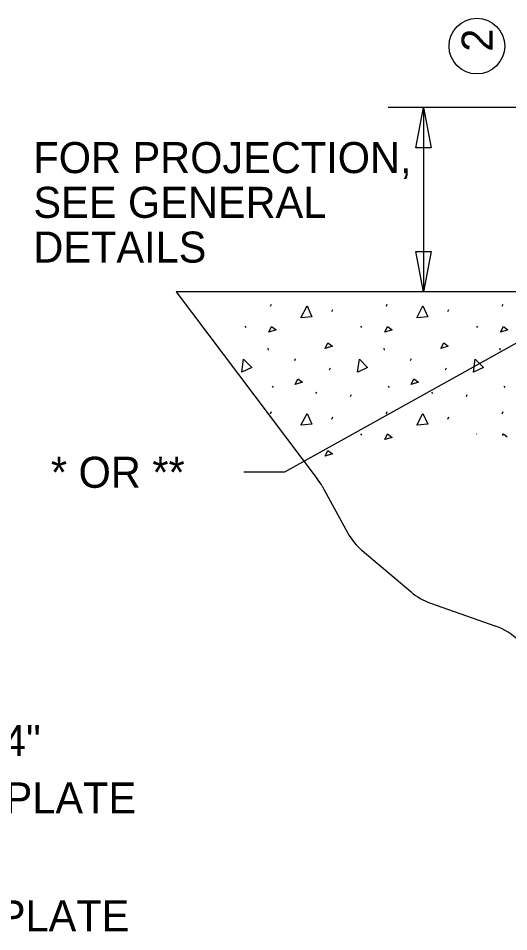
# Model space of a CAD drawing. Extents: x -125.5 to -89.4, y -5.1 to 16.9.
# Drawn here: x -120.383 to -118.408, y 10.396 to 14.074 of the extents above; entities that cross this region are included whole.
import ezdxf

# ---------------------------------------------------------------- set-up
doc = ezdxf.new("R2010")
doc.units = 0
for name, color, linetype in [('BR_AUTO DIMENSION', 7, 'Continuous'), ('BR_CONCRETE', 7, 'Continuous'), ('BR_TEXT', 7, 'Continuous'), ('Default', 7, 'Continuous')]:
    doc.layers.add(name, color=color, linetype=linetype)

msp = doc.modelspace()

# ---------------------------------------------------------------- linework, layer by layer
at = {"layer": 'BR_AUTO DIMENSION'}
for p, q in [((-117.7986, 13.7148), (-118.8938, 13.7148)), ((-118.7513, 13.7148), (-118.7513, 12.9727)), ((-119.3102, 12.2479), (-117.8689, 13.0491)), ((-119.4755, 12.2479), (-119.3102, 12.2479))]:
    msp.add_line(p, q, dxfattribs=at)
for points in [[(-118.7825, 13.5523), (-118.7513, 13.7148), (-118.72, 13.5523)], [(-118.72, 13.1352), (-118.7513, 12.9727), (-118.7825, 13.1352)]]:
    msp.add_lwpolyline(points, close=True, dxfattribs=at)
msp.add_circle((-118.5364, 13.9616), 0.1121, dxfattribs=at)
at = {"layer": 'BR_CONCRETE'}
msp.add_line((-114.1549, 12.9727), (-119.7474, 12.9727), dxfattribs=at)
at = {"layer": 'Default'}
for p, q in [((-119.7474, 12.9727), (-119.1793, 12.2195)), ((-119.3676, 12.9144), (-119.3639, 12.9227)), ((-119.2451, 12.8681), (-119.2201, 12.9153)), ((-119.2201, 12.9153), (-119.2007, 12.8718)), ((-118.901, 12.9144), (-118.8973, 12.9227)), ((-118.7784, 12.8681), (-118.7534, 12.9153)), ((-118.7534, 12.9153), (-118.734, 12.8718)), ((-118.4343, 12.9144), (-118.4306, 12.9227)), ((-119.1202, 12.8931), (-119.1165, 12.9014)), ((-118.6535, 12.8931), (-118.6498, 12.9014)), ((-119.2007, 12.8718), (-119.2441, 12.8681)), ((-118.734, 12.8718), (-118.7775, 12.8681)), ((-119.4712, 12.8339), (-119.4675, 12.8283)), ((-119.3741, 12.8098), (-119.363, 12.833)), ((-119.3445, 12.8191), (-119.3741, 12.8098)), ((-119.363, 12.833), (-119.3445, 12.8191)), ((-119.0046, 12.8339), (-119.0009, 12.8283)), ((-118.9074, 12.8098), (-118.8963, 12.833)), ((-118.8778, 12.8191), (-118.9074, 12.8098)), ((-118.8963, 12.833), (-118.8778, 12.8191)), ((-118.5379, 12.8339), (-118.5342, 12.8283)), ((-118.4408, 12.8098), (-118.4297, 12.833)), ((-118.4112, 12.8191), (-118.4408, 12.8098)), ((-118.4297, 12.833), (-118.4112, 12.8191)), ((-119.1478, 12.7437), (-119.1367, 12.7668)), ((-119.1367, 12.7668), (-119.1182, 12.753)), ((-118.6811, 12.7437), (-118.67, 12.7668)), ((-118.67, 12.7668), (-118.6515, 12.753)), ((-119.3777, 12.7452), (-119.3768, 12.7368)), ((-119.1182, 12.753), (-119.1478, 12.7437)), ((-118.911, 12.7452), (-118.9101, 12.7368)), ((-118.6515, 12.753), (-118.6811, 12.7437)), ((-118.4444, 12.7452), (-118.4434, 12.7368)), ((-119.4836, 12.6486), (-119.4762, 12.7014)), ((-119.4762, 12.7014), (-119.4431, 12.6672)), ((-119.27, 12.6961), (-119.2663, 12.7044)), ((-119.0169, 12.6486), (-119.0096, 12.7014)), ((-119.0096, 12.7014), (-118.9764, 12.6672)), ((-118.8034, 12.6961), (-118.7997, 12.7044)), ((-118.5502, 12.6486), (-118.5429, 12.7014)), ((-118.5429, 12.7014), (-118.5098, 12.6672)), ((-119.4431, 12.6672), (-119.4827, 12.6489)), ((-119.1294, 12.6581), (-119.1257, 12.6665)), ((-118.9764, 12.6672), (-119.016, 12.6489)), ((-118.6628, 12.6581), (-118.6591, 12.6665)), ((-118.5098, 12.6672), (-118.5494, 12.6489)), ((-119.2682, 12.5989), (-119.2571, 12.6221)), ((-119.2571, 12.6221), (-119.2386, 12.6082)), ((-118.8015, 12.5989), (-118.7904, 12.6221)), ((-118.7904, 12.6221), (-118.7719, 12.6082)), ((-119.3606, 12.5925), (-119.3569, 12.5869)), ((-119.2386, 12.6082), (-119.2682, 12.5989)), ((-118.8939, 12.5925), (-118.8902, 12.5869)), ((-118.7719, 12.6082), (-118.8015, 12.5989)), ((-118.4273, 12.5925), (-118.4236, 12.5869)), ((-119.186, 12.5689), (-119.1823, 12.5634)), ((-119.0453, 12.5508), (-119.0416, 12.5592)), ((-118.7193, 12.5689), (-118.7156, 12.5634)), ((-118.5786, 12.5508), (-118.5749, 12.5592)), ((-119.3676, 12.4815), (-119.3639, 12.4898)), ((-119.2451, 12.4353), (-119.2201, 12.4824)), ((-119.2201, 12.4824), (-119.2007, 12.439)), ((-119.1202, 12.4602), (-119.1165, 12.4686)), ((-118.901, 12.4815), (-118.8973, 12.4898)), ((-118.7784, 12.4353), (-118.7534, 12.4824)), ((-118.7534, 12.4824), (-118.734, 12.439)), ((-118.6535, 12.4602), (-118.6498, 12.4686)), ((-118.4343, 12.4815), (-118.4306, 12.4898)), ((-119.2007, 12.439), (-119.2441, 12.4353)), ((-118.734, 12.439), (-118.7775, 12.4353)), ((-119.0046, 12.401), (-119.0009, 12.3955)), ((-118.9074, 12.377), (-118.8963, 12.4001)), ((-118.8963, 12.4001), (-118.8778, 12.3862)), ((-118.5379, 12.401), (-118.5365, 12.3989)), ((-118.433, 12.3932), (-118.4297, 12.4001)), ((-118.4297, 12.4001), (-118.4138, 12.3882)), ((-118.8778, 12.3862), (-118.9074, 12.377)), ((-119.1478, 12.3109), (-119.1367, 12.334)), ((-119.1367, 12.334), (-119.1182, 12.3201)), ((-119.1182, 12.3201), (-119.1478, 12.3109)), ((-119.1597, 12.1893), (-119.0561, 12.0007)), ((-118.9983, 11.9301), (-118.8012, 11.7637)), ((-118.7233, 11.7191), (-118.4605, 11.6261))]:
    msp.add_line(p, q, dxfattribs=at)
for centre, start, end in [((-119.3788, 12.069), 28.7877, 37.0271), ((-118.837, 12.1211), 208.7877, 229.8326), ((-118.6399, 11.9548), 229.8326, 250.5152), ((-118.5438, 11.3904), 44.6646, 70.5152)]:
    msp.add_arc(centre, 0.25, start, end, dxfattribs=at)

# ---------------------------------------------------------------- texts
at = {"layer": 'BR_AUTO DIMENSION'}
msp.add_text('2', height=0.125, rotation=90, dxfattribs=at).set_placement((-118.4728, 13.9389))
for s, p in [('FOR PROJECTION, ', (-120.3225, 13.4502)), ('SEE GENERAL', (-120.3225, 13.27)), ('DETAILS', (-120.3225, 13.0899)), ('3" x 5" x 1\'-3 1/4"', (-121.562, 11.1031)), ('BUILD-DOWN PLATE', (-121.562, 10.8719))]:
    msp.add_text(s, height=0.125, dxfattribs=at).set_placement(p)
at = {"layer": 'BR_TEXT'}
for s, p in [('* OR **', (-120.252, 12.1833)), ('BUILD-DOWN PLATE', (-121.5894, 10.3976))]:
    msp.add_text(s, height=0.125, rotation=360, dxfattribs=at).set_placement(p)

doc.saveas('drawing.dxf')
